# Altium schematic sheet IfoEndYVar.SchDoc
size A; DocumentNumber: 3; SheetNumber: 3; SheetTotal: 8; pInstance: Corner
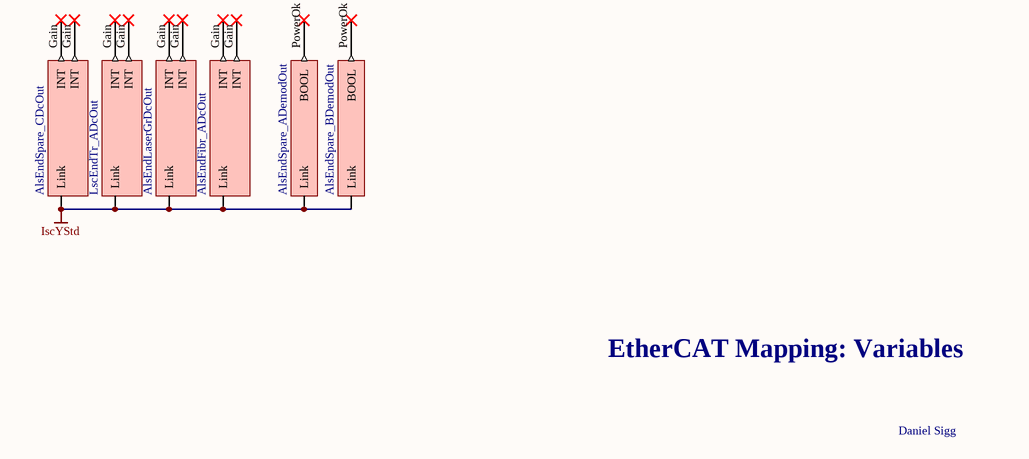
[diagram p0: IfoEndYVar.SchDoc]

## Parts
V52  AlsEndSpare_CDcOut  (no BOM)
V54  LscEndTr_ADcOut  (no BOM)
V56  AlsEndLaserGrDcOut  (no BOM)
V58  AlsEndFibr_ADcOut  (no BOM)
V60  AlsEndSpare_ADemodOut  (no BOM)
V65  AlsEndSpare_BDemodOut  (no BOM)

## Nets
IscYStd: V52.0(Link) V54.0(Link) V56.0(Link) V58.0(Link) V60.?1(Link) V65.?1(Link)

Not connected (* = marked no-connect by the designer): V52 Gain(INT)*; V54 Gain(INT)*; V56 Gain(INT)*; V58 Gain(INT)*; V60 PowerOk(BOOL)*; V65 PowerOk(BOOL)*

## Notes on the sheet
- EtherCAT Mapping: Variables
- Daniel Sigg

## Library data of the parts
V52 V54 V56 V58 = DCPower_DCPowerOutStruct: DCPowerOutStruct; BoxType: Variable; Instance: H1IscEndY Instance; PLC: H1IscEndY; Task: IscEStd
V60 V65 = Demodulator_DemodulatorOutStruct: DemodulatorOutStruct; BoxType: Variable; Instance: H1IscEndY Instance; PLC: H1IscEndY; Task: IscEStd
